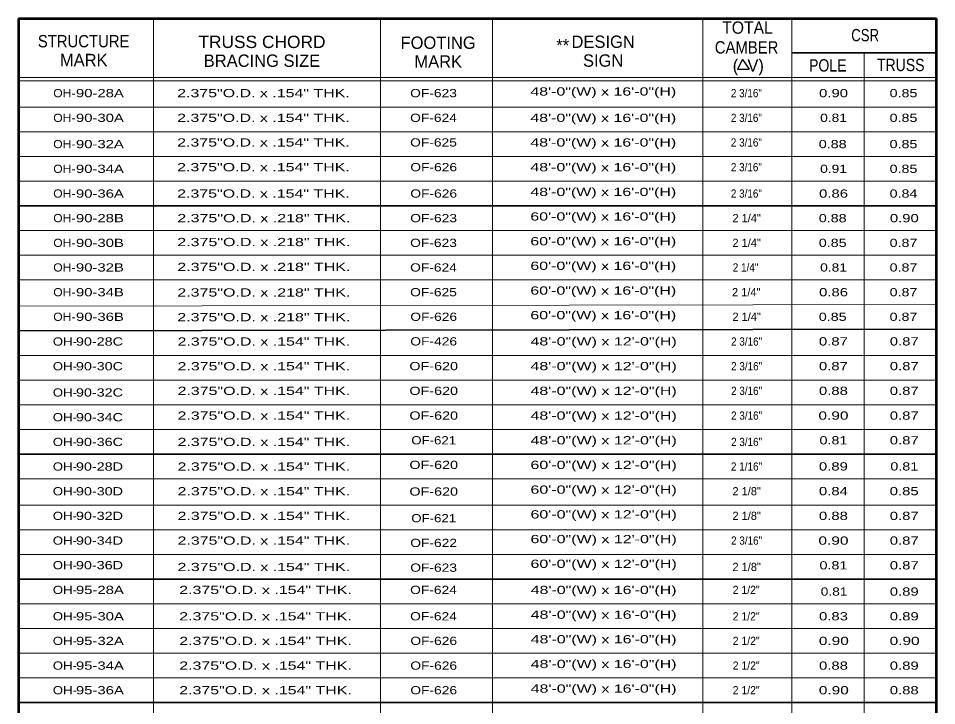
# Model space of a CAD drawing. Extents: x -34810.3 to -34803.4, y -181503.6 to -181493.6.
# Drawn here: x -34810.07 to -34803.39, y -181498.59 to -181493.59 of the extents above; entities that cross this region are included whole.
import ezdxf
from ezdxf.enums import TextEntityAlignment as Align

# ---------------------------------------------------------------- set-up
doc = ezdxf.new("R2010")
doc.units = 0
doc.header["$LTSCALE"] = 0.024
doc.layers.add('1', color=7, linetype='Continuous', lineweight=13)
doc.layers.add('13', color=7, linetype='Continuous', lineweight=25)

msp = doc.modelspace()

# ---------------------------------------------------------------- linework, layer by layer
at = {"layer": '1', "lineweight": 53}
for p, q in [((-34810.067, -181493.589), (-34810.067, -181501.286)), ((-34810.067, -181493.589), (-34803.387, -181493.589)), ((-34803.387, -181501.286), (-34803.387, -181493.589))]:
    msp.add_line(p, q, dxfattribs=at)
at = {"layer": '1'}
for p, q in [((-34809.085, -181493.589), (-34809.085, -181501.286)), ((-34809.085, -181493.589), (-34809.085, -181501.286)), ((-34807.433, -181493.589), (-34807.433, -181501.286)), ((-34806.619, -181493.589), (-34806.619, -181501.286)), ((-34805.087, -181493.589), (-34805.087, -181501.286)), ((-34804.44, -181501.286), (-34804.44, -181493.589)), ((-34803.913, -181493.84), (-34803.913, -181501.286)), ((-34803.387, -181494.02), (-34810.067, -181494.02)), ((-34803.387, -181494.044), (-34810.067, -181494.044)), ((-34803.387, -181494.235), (-34810.067, -181494.235)), ((-34803.387, -181494.415), (-34810.067, -181494.415)), ((-34803.387, -181494.594), (-34810.067, -181494.594)), ((-34803.387, -181494.774), (-34810.067, -181494.774)), ((-34803.387, -181495.133), (-34810.067, -181495.133)), ((-34803.387, -181495.313), (-34810.067, -181495.313)), ((-34803.387, -181495.492), (-34810.067, -181495.492)), ((-34803.387, -181495.672), (-34810.067, -181495.684)), ((-34803.387, -181496.043), (-34810.067, -181496.043)), ((-34803.387, -181496.222), (-34810.067, -181496.222)), ((-34803.387, -181496.402), (-34810.067, -181496.402)), ((-34803.387, -181496.582), (-34810.067, -181496.582)), ((-34803.387, -181496.941), (-34810.067, -181496.941)), ((-34803.387, -181497.132), (-34810.067, -181497.132)), ((-34803.387, -181497.312), (-34810.067, -181497.312)), ((-34803.387, -181497.491), (-34810.067, -181497.491)), ((-34803.387, -181497.851), (-34810.067, -181497.851)), ((-34803.387, -181498.03), (-34810.067, -181498.03)), ((-34803.387, -181498.21), (-34810.067, -181498.21)), ((-34803.387, -181498.389), (-34810.067, -181498.389))]:
    msp.add_line(p, q, dxfattribs=at)
at = {"layer": '1', "lineweight": 35}
for p, q in [((-34804.44, -181493.84), (-34803.387, -181493.84)), ((-34803.387, -181494.953), (-34810.067, -181494.953)), ((-34803.387, -181495.851), (-34810.067, -181495.863)), ((-34803.387, -181496.761), (-34810.067, -181496.761)), ((-34803.387, -181497.671), (-34810.067, -181497.671)), ((-34803.387, -181498.569), (-34810.067, -181498.569))]:
    msp.add_line(p, q, dxfattribs=at)
at = {"layer": '13'}
for p, q in [((-34804.799, -181493.888), (-34804.835, -181493.96)), ((-34804.799, -181493.888), (-34804.751, -181493.96)), ((-34804.835, -181493.96), (-34804.751, -181493.96))]:
    msp.add_line(p, q, dxfattribs=at)

# ---------------------------------------------------------------- texts
for s, height, width, p in [('TOTAL', 0.08978, 0.95, (-34804.763, -181493.701)), ('STRUCTURE', 0.08978, 0.9, (-34809.592, -181493.8)), (' TRUSS CHORD ', 0.08978, 1.05, (-34808.295, -181493.805)), ('CSR', 0.08978, 0.8, (-34803.907, -181493.756)), ('CAMBER', 0.08978, 0.9, (-34804.7695, -181493.845)), ('POLE', 0.08978, 0.85, (-34804.179, -181493.976)), ('TRUSS', 0.08978, 0.85, (-34803.648, -181493.973)), ('OH-', 0.05983, 1.1, (-34809.7325, -181494.163)), ('2.375"O.D. x .154" THK.', 0.05983, 1.45, (-34808.284, -181494.163)), ('OF-623', 0.06, 1.25, (-34807.047, -181494.163)), ('48\'-0"(W) x 16\'-0"(H)', 0.05983, 1.45, (-34805.812, -181494.151)), ('2 3/16"', 0.05983, 0.9, (-34804.771, -181494.163)), ('0.90', 0.05983, 1.35, (-34804.137, -181494.163)), ('0.85', 0.05983, 1.3, (-34803.628, -181494.163)), ('OH-', 0.05983, 1.1, (-34809.7325, -181494.343)), ('2.375"O.D. x .154" THK.', 0.05983, 1.45, (-34808.284, -181494.343)), ('OF-624', 0.06, 1.25, (-34807.047, -181494.343)), ('48\'-0"(W) x 16\'-0"(H)', 0.05983, 1.45, (-34805.812, -181494.343)), ('2 3/16"', 0.05983, 0.9, (-34804.771, -181494.343)), ('0.81', 0.05983, 1.25, (-34804.137, -181494.343)), ('0.85', 0.05983, 1.3, (-34803.628, -181494.343)), ('2.375"O.D. x .154" THK.', 0.05983, 1.45, (-34808.284, -181494.522)), ('OF-625', 0.06, 1.25, (-34807.047, -181494.522)), ('48\'-0"(W) x 16\'-0"(H)', 0.05983, 1.45, (-34805.812, -181494.522)), ('2 3/16"', 0.05983, 0.9, (-34804.771, -181494.522)), ('OH-', 0.05983, 1.1, (-34809.7325, -181494.534)), ('0.88', 0.05983, 1.3, (-34804.143, -181494.534)), ('0.85', 0.05983, 1.3, (-34803.628, -181494.534)), ('OH-', 0.05983, 1.1, (-34809.7325, -181494.714)), ('2.375"O.D. x .154" THK.', 0.05983, 1.45, (-34808.284, -181494.702)), ('OF-626', 0.06, 1.25, (-34807.0455, -181494.702)), ('48\'-0"(W) x 16\'-0"(H)', 0.05983, 1.45, (-34805.812, -181494.702)), ('2 3/16"', 0.05983, 0.9, (-34804.771, -181494.702)), ('0.91', 0.05983, 1.25, (-34804.137, -181494.714)), ('0.85', 0.05983, 1.3, (-34803.628, -181494.714)), ('OH-', 0.05983, 1.1, (-34809.7325, -181494.894)), ('2.375"O.D. x .154" THK.', 0.05983, 1.45, (-34808.284, -181494.894)), ('OF-626', 0.06, 1.25, (-34807.0455, -181494.894)), ('48\'-0"(W) x 16\'-0"(H)', 0.05983, 1.45, (-34805.812, -181494.882)), ('2 3/16"', 0.05983, 0.9, (-34804.771, -181494.894)), ('0.86', 0.05983, 1.35, (-34804.137, -181494.894)), ('0.84', 0.05983, 1.3, (-34803.628, -181494.894)), ('60\'-0"(W) x 16\'-0"(H)', 0.05983, 1.45, (-34805.812, -181495.061)), ('OH-', 0.05983, 1.1, (-34809.7325, -181495.073)), ('2.375"O.D. x .218" THK.', 0.06, 1.45, (-34808.281, -181495.073)), ('OF-623', 0.06, 1.25, (-34807.046, -181495.073)), ('0.88', 0.05983, 1.3, (-34804.143, -181495.073)), ('0.90', 0.05983, 1.35, (-34803.622, -181495.073)), ('OH-', 0.05983, 1.1, (-34809.7325, -181495.253)), ('2.375"O.D. x .218" THK.', 0.06, 1.45, (-34808.281, -181495.247)), ('OF-623', 0.06, 1.25, (-34807.047, -181495.253)), ('60\'-0"(W) x 16\'-0"(H)', 0.05983, 1.45, (-34805.812, -181495.241)), ('0.85', 0.05983, 1.3, (-34804.143, -181495.253)), ('0.87', 0.05983, 1.3, (-34803.628, -181495.253)), ('OH-', 0.05983, 1.1, (-34809.7325, -181495.432)), ('2.375"O.D. x .218" THK.', 0.06, 1.45, (-34808.281, -181495.428)), ('OF-624', 0.06, 1.25, (-34807.047, -181495.432)), ('60\'-0"(W) x 16\'-0"(H)', 0.05983, 1.45, (-34805.812, -181495.42)), ('2 1/4"', 0.05983, 0.9, (-34804.777, -181495.432)), ('0.81', 0.05983, 1.25, (-34804.137, -181495.432)), ('0.87', 0.05983, 1.3, (-34803.628, -181495.432)), ('OH-', 0.05983, 1.1, (-34809.7325, -181495.612)), ('2.375"O.D. x .218" THK.', 0.06, 1.45, (-34808.281, -181495.614)), ('OF-625', 0.06, 1.25, (-34807.047, -181495.612)), ('60\'-0"(W) x 16\'-0"(H)', 0.05983, 1.45, (-34805.812, -181495.6)), ('0.86', 0.05983, 1.35, (-34804.137, -181495.612)), ('0.87', 0.05983, 1.3, (-34803.628, -181495.612)), ('OH-', 0.05983, 1.1, (-34809.7325, -181495.791)), ('2.375"O.D. x .218" THK.', 0.06, 1.45, (-34808.281, -181495.794)), ('OF-626', 0.06, 1.25, (-34807.0455, -181495.791)), ('60\'-0"(W) x 16\'-0"(H)', 0.05983, 1.45, (-34805.812, -181495.779)), ('0.85', 0.05983, 1.3, (-34804.143, -181495.791)), ('0.87', 0.05983, 1.3, (-34803.628, -181495.791)), ('OH-', 0.05983, 1.2, (-34809.7285, -181495.971)), ('2.375"O.D. x .154" THK.', 0.05983, 1.45, (-34808.281, -181495.971)), ('OF-426', 0.06, 1.25, (-34807.0455, -181495.97)), ('48\'-0"(W) x 12\'-0"(H)', 0.06, 1.45, (-34805.8095, -181495.97)), ('2 3/16"', 0.05983, 0.9, (-34804.7695, -181495.971)), ('0.87', 0.06, 1.35, (-34804.138, -181495.97)), ('0.87', 0.05983, 1.35, (-34803.6225, -181495.97)), ('OH-', 0.05983, 1.2, (-34809.7285, -181496.151)), ('2.375"O.D. x .154" THK.', 0.05983, 1.45, (-34808.281, -181496.151)), ('OF-620', 0.06, 1.3, (-34807.0455, -181496.15)), ('48\'-0"(W) x 12\'-0"(H)', 0.06, 1.45, (-34805.8095, -181496.15)), ('2 3/16"', 0.05983, 0.9, (-34804.7695, -181496.151)), ('0.87', 0.06, 1.35, (-34804.138, -181496.15)), ('0.87', 0.05983, 1.35, (-34803.6225, -181496.15)), ('48\'-0"(W) x 12\'-0"(H)', 0.06, 1.45, (-34805.8095, -181496.33)), ('2 3/16"', 0.05983, 0.9, (-34804.7695, -181496.33)), ('OH-', 0.05983, 1.2, (-34809.7285, -181496.342)), ('2.375"O.D. x .154" THK.', 0.05983, 1.45, (-34808.281, -181496.33)), ('OF-620', 0.06, 1.3, (-34807.0455, -181496.33)), ('0.88', 0.06, 1.35, (-34804.138, -181496.33)), ('0.87', 0.05983, 1.35, (-34803.6225, -181496.33)), ('OH-', 0.05983, 1.2, (-34809.7285, -181496.522)), ('2.375"O.D. x .154" THK.', 0.05983, 1.45, (-34808.281, -181496.51)), ('OF-620', 0.06, 1.3, (-34807.0455, -181496.51)), ('48\'-0"(W) x 12\'-0"(H)', 0.06, 1.45, (-34805.8095, -181496.51)), ('2 3/16"', 0.05983, 0.9, (-34804.7695, -181496.51)), ('0.90', 0.06, 1.4, (-34804.1375, -181496.51)), ('0.87', 0.05983, 1.35, (-34803.6225, -181496.51)), ('OH-', 0.05983, 1.2, (-34809.7285, -181496.702)), ('2.375"O.D. x .154" THK.', 0.05983, 1.45, (-34808.281, -181496.702)), ('OF-621', 0.06, 1.2, (-34807.0455, -181496.69)), ('48\'-0"(W) x 12\'-0"(H)', 0.06, 1.45, (-34805.8095, -181496.69)), ('2 3/16"', 0.05983, 0.9, (-34804.7695, -181496.702)), ('0.81', 0.06, 1.3, (-34804.1375, -181496.69)), ('0.87', 0.05983, 1.35, (-34803.6225, -181496.69)), ('OH-', 0.05983, 1.2, (-34809.7285, -181496.881)), ('2.375"O.D. x .154" THK.', 0.05983, 1.45, (-34808.281, -181496.881)), ('OF-620', 0.06, 1.3, (-34807.0455, -181496.869)), ('60\'-0"(W) x 12\'-0"(H)', 0.06, 1.45, (-34805.8095, -181496.869)), ('2 1/16"', 0.06, 0.9, (-34804.77, -181496.881)), ('0.89', 0.06, 1.35, (-34804.138, -181496.88)), ('0.81', 0.06, 1.3, (-34803.6225, -181496.88)), ('OH-', 0.05983, 1.2, (-34809.7285, -181497.061)), ('2.375"O.D. x .154" THK.', 0.05983, 1.45, (-34808.281, -181497.061)), ('OF-620', 0.06, 1.3, (-34807.0455, -181497.063)), ('60\'-0"(W) x 12\'-0"(H)', 0.06, 1.45, (-34805.8095, -181497.049)), ('0.84', 0.06, 1.35, (-34804.138, -181497.06)), ('0.85', 0.06, 1.35, (-34803.623, -181497.06)), ('OH-', 0.05983, 1.2, (-34809.7285, -181497.24)), ('2.375"O.D. x .154" THK.', 0.05983, 1.45, (-34808.281, -181497.24)), ('OF-621', 0.06, 1.2, (-34807.0455, -181497.257)), ('60\'-0"(W) x 12\'-0"(H)', 0.06, 1.45, (-34805.8095, -181497.229)), ('0.88', 0.06, 1.35, (-34804.138, -181497.24)), ('0.87', 0.05983, 1.35, (-34803.6225, -181497.24)), ('OH-', 0.05983, 1.2, (-34809.7285, -181497.42)), ('2.375"O.D. x .154" THK.', 0.05983, 1.45, (-34808.281, -181497.42)), ('OF-622', 0.06, 1.25, (-34807.046, -181497.437)), ('60\'-0"(W) x 12\'-0"(H)', 0.06, 1.45, (-34805.8095, -181497.409)), ('2 3/16"', 0.05983, 0.9, (-34804.7695, -181497.42)), ('0.90', 0.06, 1.4, (-34804.1375, -181497.42)), ('0.87', 0.05983, 1.35, (-34803.6225, -181497.42)), ('60\'-0"(W) x 12\'-0"(H)', 0.06, 1.45, (-34805.8095, -181497.589)), ('OH-', 0.05983, 1.2, (-34809.7285, -181497.599)), ('2.375"O.D. x .154" THK.', 0.05983, 1.45, (-34808.281, -181497.612)), ('OF-623', 0.06, 1.25, (-34807.046, -181497.617)), ('0.81', 0.06, 1.3, (-34804.1375, -181497.6)), ('0.87', 0.05983, 1.35, (-34803.6225, -181497.6)), ('OH-', 0.05983, 1.2, (-34809.7285, -181497.779)), ('2.375"O.D. x .154" THK.', 0.05983, 1.45, (-34808.269, -181497.779)), ('OF-624', 0.06, 1.25, (-34807.047, -181497.779)), ('48\'-0"(W) x 16\'-0"(H)', 0.05983, 1.45, (-34805.8095, -181497.779)), ('2 1/2"', 0.05983, 0.95, (-34804.7725, -181497.779)), ('0.81', 0.05983, 1.25, (-34804.133, -181497.791)), ('0.89', 0.05983, 1.35, (-34803.6225, -181497.791)), ('OH-', 0.05983, 1.2, (-34809.7285, -181497.971)), ('2.375"O.D. x .154" THK.', 0.05983, 1.45, (-34808.269, -181497.971)), ('OF-624', 0.06, 1.25, (-34807.047, -181497.971)), ('48\'-0"(W) x 16\'-0"(H)', 0.05983, 1.45, (-34805.8095, -181497.959)), ('2 1/2"', 0.05983, 0.95, (-34804.7725, -181497.971)), ('0.83', 0.05983, 1.35, (-34804.1375, -181497.971)), ('0.89', 0.05983, 1.35, (-34803.6225, -181497.971)), ('OH-', 0.05983, 1.2, (-34809.7285, -181498.15)), ('2.375"O.D. x .154" THK.', 0.05983, 1.45, (-34808.269, -181498.15)), ('OF-626', 0.06, 1.25, (-34807.0455, -181498.15)), ('48\'-0"(W) x 16\'-0"(H)', 0.05983, 1.45, (-34805.8095, -181498.138)), ('2 1/2"', 0.05983, 0.95, (-34804.7725, -181498.15)), ('0.90', 0.05983, 1.4, (-34804.135, -181498.15)), ('0.90', 0.05983, 1.4, (-34803.62, -181498.15)), ('OH-', 0.05983, 1.2, (-34809.7285, -181498.33)), ('2.375"O.D. x .154" THK.', 0.05983, 1.45, (-34808.269, -181498.33)), ('OF-626', 0.06, 1.25, (-34807.0455, -181498.33)), ('48\'-0"(W) x 16\'-0"(H)', 0.05983, 1.45, (-34805.8095, -181498.318)), ('2 1/2"', 0.05983, 0.95, (-34804.7725, -181498.33)), ('0.88', 0.05983, 1.35, (-34804.1375, -181498.33)), ('0.89', 0.05983, 1.35, (-34803.6225, -181498.33)), ('OH-', 0.05983, 1.2, (-34809.7285, -181498.509)), ('2.375"O.D. x .154" THK.', 0.05983, 1.45, (-34808.269, -181498.509)), ('OF-626', 0.06, 1.25, (-34807.0455, -181498.509)), ('48\'-0"(W) x 16\'-0"(H)', 0.05983, 1.45, (-34805.8095, -181498.497)), ('2 1/2"', 0.05983, 0.95, (-34804.7725, -181498.509)), ('0.90', 0.05983, 1.4, (-34804.135, -181498.509)), ('0.88', 0.05983, 1.35, (-34803.6225, -181498.509))]:
    msp.add_text(s, height=height, dxfattribs=dict(at, width=width)).set_placement(p, align=Align.CENTER)
for s, height, p in [('FOOTING', 0.08978, (-34807.0135, -181493.811)), ('DESIGN', 0.08978, (-34805.813, -181493.804)), ('**', 0.09, (-34806.107, -181493.83)), ('MARK', 0.08978, (-34809.5915, -181493.937)), ('BRACING SIZE', 0.08978, (-34808.295, -181493.942)), ('MARK', 0.08978, (-34807.0125, -181493.948)), ('SIGN', 0.08978, (-34805.813, -181493.941)), ('(  V)', 0.08978, (-34804.757, -181493.977)), ('2 1/4"', 0.06, (-34804.769, -181495.073)), ('2 1/4"', 0.06, (-34804.769, -181495.253)), ('2 1/4"', 0.06, (-34804.772, -181495.612)), ('2 1/4"', 0.06, (-34804.769, -181495.791)), ('2 1/8"', 0.06, (-34804.769, -181497.061)), ('2 1/8"', 0.06, (-34804.769, -181497.24)), ('2 1/8"', 0.06, (-34804.769, -181497.612))]:
    msp.add_text(s, height=height, dxfattribs=at).set_placement(p, align=Align.CENTER)
for s, height, width, p in [('90-28A', 0.05983, 1.35, (-34809.648, -181494.163)), ('90-30A', 0.05983, 1.35, (-34809.648, -181494.343)), ('90-32A', 0.05983, 1.35, (-34809.648, -181494.534)), ('90-34A', 0.05983, 1.35, (-34809.648, -181494.714)), ('90-36A', 0.05983, 1.35, (-34809.648, -181494.894)), ('90-28B', 0.05983, 1.35, (-34809.648, -181495.073)), ('90-30B', 0.05983, 1.35, (-34809.648, -181495.253)), ('90-32B', 0.05983, 1.35, (-34809.648, -181495.432)), ('90-34B', 0.05983, 1.35, (-34809.648, -181495.612)), ('90-36B', 0.05983, 1.35, (-34809.648, -181495.791)), ('90-28C', 0.06, 1.3, (-34809.648, -181495.971)), ('90-30C', 0.06, 1.3, (-34809.648, -181496.151)), ('90-32C', 0.06, 1.3, (-34809.648, -181496.342)), ('90-34C', 0.06, 1.3, (-34809.648, -181496.522)), ('90-36C', 0.06, 1.3, (-34809.648, -181496.702)), ('90-28D', 0.06, 1.3, (-34809.648, -181496.881)), ('90-30D', 0.06, 1.3, (-34809.648, -181497.061)), ('90-32D', 0.06, 1.3, (-34809.648, -181497.24)), ('90-34D', 0.06, 1.3, (-34809.648, -181497.42)), ('90-36D', 0.06, 1.3, (-34809.648, -181497.599)), ('95-28A', 0.05983, 1.35, (-34809.648, -181497.779)), ('95-30A', 0.05983, 1.35, (-34809.648, -181497.971)), ('95-32A', 0.05983, 1.35, (-34809.648, -181498.15)), ('95-34A', 0.05983, 1.35, (-34809.648, -181498.33)), ('95-36A', 0.05983, 1.35, (-34809.648, -181498.509))]:
    msp.add_text(s, height=height, dxfattribs=dict(at, width=width)).set_placement(p)

doc.saveas('drawing.dxf')
